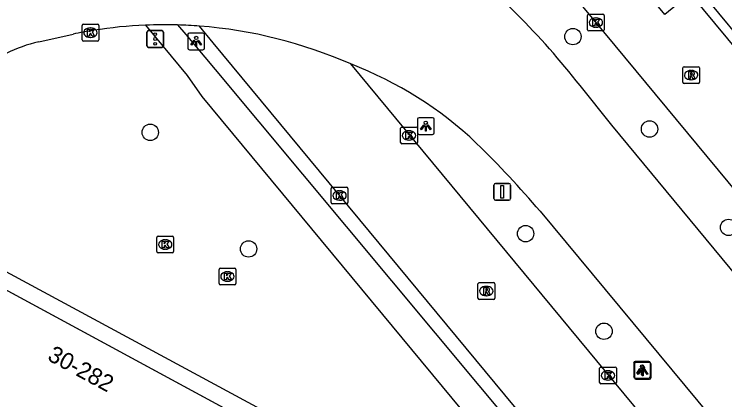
# Model space of a CAD drawing. Extents: x 159489 to 160304, y 383826 to 384530.
# Drawn here: x 159949.7 to 159992.11, y 384232.46 to 384255.48 of the extents above; entities that cross this region are included whole.
import ezdxf

# ---------------------------------------------------------------- set-up
doc = ezdxf.new("R2010")
doc.units = 0
for name, color, linetype in [('IMGEO_Boom', 7, 'Continuous'), ('IMGEO_Fietspad_gesloten', 7, 'Continuous'), ('IMGEO_Kolk', 7, 'Continuous'), ('IMGEO_Lichtpunt', 7, 'Continuous'), ('IMGEO_OVBaan_gesloten', 7, 'Continuous'), ('IMGEO_Pand', 7, 'Continuous'), ('IMGEO_Pand_nummerreeks', 7, 'Continuous'), ('IMGEO_Pand_overbouw', 7, 'Continuous'), ('IMGEO_Rijbaan_lokaal_gesloten', 7, 'Continuous'), ('IMGEO_Rioolput', 7, 'Continuous'), ('IMGEO_Verkeersbordpaal', 7, 'Continuous'), ('IMGEO_Verkeersregelinstallatiepaal', 7, 'Continuous'), ('IMGEO_Voetpad_open', 7, 'Continuous')]:
    doc.layers.add(name, color=color, linetype=linetype)

msp = doc.modelspace()

# ---------------------------------------------------------------- linework, layer by layer
at = {"layer": 'IMGEO_Boom'}
for centre in [(159983.042, 384254.142), (159957.82, 384248.425), (159987.615, 384248.624), (159992.334, 384242.748), (159980.22, 384242.376), (159963.688, 384241.466), (159984.896, 384236.553)]:
    msp.add_circle(centre, 0.489, dxfattribs=at)
at = {"layer": 'IMGEO_Fietspad_gesloten'}
for points in [[(159957.532, 384254.825), (159960.033, 384251.817), (159960.897, 384250.561), (160029.527, 384167.731), (160030.452, 384166.645)], [(159959.452, 384254.838), (159959.937, 384254.261), (159961.686, 384252.179), (160032.453, 384167.34)]]:
    msp.add_lwpolyline(points, dxfattribs=at)
at = {"layer": 'IMGEO_Kolk'}
for p, q in [((159983.91, 384254.552), (159983.91, 384255.404)), ((159983.985, 384255.478), (159984.837, 384255.478)), ((159984.398, 384255.258), (159984.423, 384255.258)), ((159984.911, 384255.404), (159984.911, 384254.552)), ((159953.753, 384253.951), (159953.753, 384254.803)), ((159953.828, 384254.877), (159954.68, 384254.877)), ((159954.754, 384254.803), (159954.754, 384253.951)), ((159954.241, 384254.657), (159954.266, 384254.657)), ((159984.837, 384254.478), (159983.985, 384254.478)), ((159984.421, 384254.698), (159984.396, 384254.698)), ((159954.264, 384254.097), (159954.239, 384254.097)), ((159954.68, 384253.877), (159953.828, 384253.877)), ((159972.761, 384247.814), (159972.761, 384248.666)), ((159972.836, 384248.74), (159973.688, 384248.74)), ((159973.249, 384248.52), (159973.274, 384248.52)), ((159973.762, 384248.666), (159973.762, 384247.814)), ((159973.688, 384247.74), (159972.836, 384247.74)), ((159973.272, 384247.96), (159973.247, 384247.96)), ((159968.614, 384244.23), (159968.614, 384245.082)), ((159968.689, 384245.156), (159969.541, 384245.156)), ((159969.615, 384245.082), (159969.615, 384244.23)), ((159969.102, 384244.936), (159969.127, 384244.936)), ((159969.125, 384244.376), (159969.1, 384244.376)), ((159969.541, 384244.156), (159968.689, 384244.156)), ((159958.212, 384241.304), (159958.212, 384242.156)), ((159958.287, 384242.23), (159959.139, 384242.23)), ((159959.213, 384242.156), (159959.213, 384241.304)), ((159958.7, 384242.01), (159958.725, 384242.01)), ((159959.139, 384241.23), (159958.287, 384241.23)), ((159958.723, 384241.45), (159958.698, 384241.45)), ((159961.929, 384239.393), (159961.929, 384240.245)), ((159962.004, 384240.319), (159962.856, 384240.319)), ((159962.417, 384240.099), (159962.442, 384240.099)), ((159962.93, 384240.245), (159962.93, 384239.393)), ((159962.44, 384239.539), (159962.415, 384239.539)), ((159962.856, 384239.319), (159962.004, 384239.319)), ((159984.638, 384233.485), (159984.638, 384234.337)), ((159984.713, 384234.411), (159985.565, 384234.411)), ((159985.126, 384234.191), (159985.151, 384234.191)), ((159985.639, 384234.337), (159985.639, 384233.485)), ((159985.149, 384233.631), (159985.124, 384233.631)), ((159985.565, 384233.411), (159984.713, 384233.411))]:
    msp.add_line(p, q, dxfattribs=at)
for points in [[(159983.91, 384254.552), (159983.91, 384255.404)], [(159983.985, 384255.478), (159984.837, 384255.478)], [(159984.911, 384255.404), (159984.911, 384254.552)], [(159953.753, 384253.951), (159953.753, 384254.803)], [(159953.828, 384254.877), (159954.68, 384254.877)], [(159954.754, 384254.803), (159954.754, 384253.951)], [(159984.231, 384255.178), (159984.354, 384255.178), (159984.354, 384255.027), (159984.484, 384255.178), (159984.648, 384255.178), (159984.502, 384255.027), (159984.655, 384254.778), (159984.503, 384254.778), (159984.418, 384254.942), (159984.354, 384254.875), (159984.354, 384254.778), (159984.231, 384254.778), (159984.231, 384255.178)], [(159954.074, 384254.577), (159954.197, 384254.577), (159954.197, 384254.426), (159954.327, 384254.577), (159954.491, 384254.577), (159954.345, 384254.426), (159954.498, 384254.177), (159954.346, 384254.177), (159954.261, 384254.341), (159954.197, 384254.274), (159954.197, 384254.177), (159954.074, 384254.177), (159954.074, 384254.577)], [(159984.837, 384254.478), (159983.985, 384254.478)], [(159954.68, 384253.877), (159953.828, 384253.877)], [(159972.761, 384247.814), (159972.761, 384248.666)], [(159972.836, 384248.74), (159973.688, 384248.74)], [(159973.082, 384248.44), (159973.205, 384248.44), (159973.205, 384248.289), (159973.335, 384248.44), (159973.499, 384248.44), (159973.353, 384248.289), (159973.506, 384248.04), (159973.354, 384248.04), (159973.269, 384248.204), (159973.205, 384248.137), (159973.205, 384248.04), (159973.082, 384248.04), (159973.082, 384248.44)], [(159973.762, 384248.666), (159973.762, 384247.814)], [(159973.688, 384247.74), (159972.836, 384247.74)], [(159968.614, 384244.23), (159968.614, 384245.082)], [(159968.689, 384245.156), (159969.541, 384245.156)], [(159969.615, 384245.082), (159969.615, 384244.23)], [(159968.935, 384244.856), (159969.058, 384244.856), (159969.058, 384244.705), (159969.188, 384244.856), (159969.352, 384244.856), (159969.206, 384244.705), (159969.359, 384244.456), (159969.207, 384244.456), (159969.122, 384244.62), (159969.058, 384244.553), (159969.058, 384244.456), (159968.935, 384244.456), (159968.935, 384244.856)], [(159969.541, 384244.156), (159968.689, 384244.156)], [(159958.212, 384241.304), (159958.212, 384242.156)], [(159958.287, 384242.23), (159959.139, 384242.23)], [(159959.213, 384242.156), (159959.213, 384241.304)], [(159958.533, 384241.93), (159958.656, 384241.93), (159958.656, 384241.779), (159958.786, 384241.93), (159958.95, 384241.93), (159958.804, 384241.779), (159958.957, 384241.53), (159958.805, 384241.53), (159958.72, 384241.694), (159958.656, 384241.627), (159958.656, 384241.53), (159958.533, 384241.53), (159958.533, 384241.93)], [(159959.139, 384241.23), (159958.287, 384241.23)], [(159961.929, 384239.393), (159961.929, 384240.245)], [(159962.004, 384240.319), (159962.856, 384240.319)], [(159962.25, 384240.019), (159962.373, 384240.019), (159962.373, 384239.868), (159962.503, 384240.019), (159962.667, 384240.019), (159962.521, 384239.868), (159962.674, 384239.619), (159962.522, 384239.619), (159962.437, 384239.783), (159962.373, 384239.716), (159962.373, 384239.619), (159962.25, 384239.619), (159962.25, 384240.019)], [(159962.93, 384240.245), (159962.93, 384239.393)], [(159962.856, 384239.319), (159962.004, 384239.319)], [(159984.638, 384233.485), (159984.638, 384234.337)], [(159984.713, 384234.411), (159985.565, 384234.411)], [(159984.959, 384234.111), (159985.082, 384234.111), (159985.082, 384233.96), (159985.212, 384234.111), (159985.376, 384234.111), (159985.23, 384233.96), (159985.383, 384233.711), (159985.231, 384233.711), (159985.146, 384233.875), (159985.082, 384233.808), (159985.082, 384233.711), (159984.959, 384233.711), (159984.959, 384234.111)], [(159985.639, 384234.337), (159985.639, 384233.485)], [(159985.565, 384233.411), (159984.713, 384233.411)]]:
    msp.add_lwpolyline(points, dxfattribs=at)
for centre, start, end in [((159983.987, 384255.402), 91.552, 178.448), ((159983.987, 384255.402), 91.552, 178.448), ((159984.835, 384255.402), 1.552, 88.448), ((159984.835, 384255.402), 1.552, 88.448), ((159953.83, 384254.801), 91.552, 178.448), ((159953.83, 384254.801), 91.552, 178.448), ((159954.678, 384254.801), 1.552, 88.448), ((159954.678, 384254.801), 1.552, 88.448), ((159983.987, 384254.554), 181.552, 268.448), ((159983.987, 384254.554), 181.552, 268.448), ((159984.835, 384254.554), 271.552, 358.448), ((159984.835, 384254.554), 271.552, 358.448), ((159953.83, 384253.953), 181.552, 268.448), ((159953.83, 384253.953), 181.552, 268.448), ((159954.678, 384253.953), 271.552, 358.448), ((159954.678, 384253.953), 271.552, 358.448), ((159972.838, 384248.664), 91.552, 178.448), ((159972.838, 384248.664), 91.552, 178.448), ((159973.686, 384248.664), 1.552, 88.448), ((159973.686, 384248.664), 1.552, 88.448), ((159972.838, 384247.816), 181.552, 268.448), ((159972.838, 384247.816), 181.552, 268.448), ((159973.686, 384247.816), 271.552, 358.448), ((159973.686, 384247.816), 271.552, 358.448), ((159968.691, 384245.08), 91.552, 178.448), ((159968.691, 384245.08), 91.552, 178.448), ((159969.539, 384245.08), 1.552, 88.448), ((159969.539, 384245.08), 1.552, 88.448), ((159968.691, 384244.232), 181.552, 268.448), ((159968.691, 384244.232), 181.552, 268.448), ((159969.539, 384244.232), 271.552, 358.448), ((159969.539, 384244.232), 271.552, 358.448), ((159958.289, 384242.154), 91.552, 178.448), ((159958.289, 384242.154), 91.552, 178.448), ((159959.137, 384242.154), 1.552, 88.448), ((159959.137, 384242.154), 1.552, 88.448), ((159958.289, 384241.306), 181.552, 268.448), ((159958.289, 384241.306), 181.552, 268.448), ((159959.137, 384241.306), 271.552, 358.448), ((159959.137, 384241.306), 271.552, 358.448), ((159962.006, 384240.243), 91.552, 178.448), ((159962.006, 384240.243), 91.552, 178.448), ((159962.854, 384240.243), 1.552, 88.448), ((159962.854, 384240.243), 1.552, 88.448), ((159962.006, 384239.395), 181.552, 268.448), ((159962.006, 384239.395), 181.552, 268.448), ((159962.854, 384239.395), 271.552, 358.448), ((159962.854, 384239.395), 271.552, 358.448), ((159984.715, 384234.335), 91.552, 178.448), ((159984.715, 384234.335), 91.552, 178.448), ((159985.563, 384234.335), 1.552, 88.448), ((159985.563, 384234.335), 1.552, 88.448), ((159984.715, 384233.487), 181.552, 268.448), ((159984.715, 384233.487), 181.552, 268.448), ((159985.563, 384233.487), 271.552, 358.448), ((159985.563, 384233.487), 271.552, 358.448)]:
    msp.add_arc(centre, 0.0765, start, end, dxfattribs=at)
for centre, major_axis, ratio, start_param, end_param in [((159984.397, 384254.978), (-0.387, 0.002), 0.722429, 4.712389, 7.853982), ((159984.422, 384254.978), (-0.39, 0.002), 0.717154, 1.570796, 4.712389), ((159954.24, 384254.377), (-0.387, 0.002), 0.722429, 4.712389, 7.853982), ((159954.265, 384254.377), (-0.39, 0.002), 0.717154, 1.570796, 4.712389), ((159973.248, 384248.24), (-0.387, 0.002), 0.722429, 4.712389, 7.853982), ((159973.273, 384248.24), (-0.39, 0.002), 0.717154, 1.570796, 4.712389), ((159969.101, 384244.656), (-0.387, 0.002), 0.722429, 4.712389, 7.853982), ((159969.126, 384244.656), (-0.39, 0.002), 0.717154, 1.570796, 4.712389), ((159958.699, 384241.73), (-0.387, 0.002), 0.722429, 4.712389, 7.853982), ((159958.724, 384241.73), (-0.39, 0.002), 0.717154, 1.570796, 4.712389), ((159962.416, 384239.819), (-0.387, 0.002), 0.722429, 4.712389, 7.853982), ((159962.441, 384239.819), (-0.39, 0.002), 0.717154, 1.570796, 4.712389), ((159985.125, 384233.911), (-0.387, 0.002), 0.722429, 4.712389, 7.853982), ((159985.15, 384233.911), (-0.39, 0.002), 0.717154, 1.570796, 4.712389)]:
    msp.add_ellipse(centre, major_axis=major_axis, ratio=ratio, start_param=start_param, end_param=end_param, dxfattribs=at)
at = {"layer": 'IMGEO_Lichtpunt'}
for p, q in [((159960.967, 384254.356), (159960.159, 384254.356)), ((159960.967, 384254.356), (159960.159, 384254.356)), ((159960.065, 384254.261), (159960.065, 384253.454)), ((159960.065, 384254.261), (159960.065, 384253.454)), ((159961.061, 384253.454), (159961.061, 384254.261)), ((159961.061, 384253.454), (159961.061, 384254.261)), ((159960.159, 384253.36), (159960.967, 384253.36)), ((159960.159, 384253.36), (159960.967, 384253.36)), ((159974.667, 384249.3), (159973.859, 384249.3)), ((159974.667, 384249.3), (159973.859, 384249.3)), ((159973.765, 384249.205), (159973.765, 384248.398)), ((159973.765, 384249.205), (159973.765, 384248.398)), ((159974.761, 384248.398), (159974.761, 384249.205)), ((159974.761, 384248.398), (159974.761, 384249.205)), ((159973.859, 384248.304), (159974.667, 384248.304)), ((159973.859, 384248.304), (159974.667, 384248.304)), ((159986.668, 384234.654), (159986.668, 384233.847)), ((159986.668, 384234.654), (159986.668, 384233.847)), ((159986.709, 384234.59), (159986.709, 384233.783)), ((159986.709, 384234.59), (159986.709, 384233.783)), ((159987.57, 384234.749), (159986.762, 384234.749)), ((159987.57, 384234.749), (159986.762, 384234.749)), ((159987.611, 384234.685), (159986.803, 384234.685)), ((159987.611, 384234.685), (159986.803, 384234.685)), ((159987.664, 384233.847), (159987.664, 384234.654)), ((159987.664, 384233.847), (159987.664, 384234.654)), ((159987.705, 384233.783), (159987.705, 384234.59)), ((159987.705, 384233.783), (159987.705, 384234.59)), ((159986.762, 384233.753), (159987.57, 384233.753)), ((159986.762, 384233.753), (159987.57, 384233.753)), ((159986.803, 384233.689), (159987.611, 384233.689)), ((159986.803, 384233.689), (159987.611, 384233.689))]:
    msp.add_line(p, q, dxfattribs=at)
for points in [[(159960.439, 384253.925), (159960.478, 384253.897), (159960.29, 384253.635), (159960.252, 384253.662), (159960.439, 384253.925)], [(159960.651, 384253.897), (159960.689, 384253.924), (159960.876, 384253.662), (159960.837, 384253.634), (159960.651, 384253.897)], [(159960.541, 384253.877), (159960.588, 384253.877), (159960.588, 384253.555), (159960.541, 384253.555), (159960.541, 384253.877)], [(159974.139, 384248.869), (159974.178, 384248.841), (159973.99, 384248.579), (159973.952, 384248.606), (159974.139, 384248.869)], [(159974.351, 384248.841), (159974.389, 384248.868), (159974.576, 384248.606), (159974.537, 384248.578), (159974.351, 384248.841)], [(159974.241, 384248.821), (159974.288, 384248.821), (159974.288, 384248.499), (159974.241, 384248.499), (159974.241, 384248.821)], [(159987.042, 384234.318), (159987.081, 384234.29), (159986.893, 384234.028), (159986.855, 384234.055), (159987.042, 384234.318)], [(159987.083, 384234.254), (159987.122, 384234.226), (159986.934, 384233.964), (159986.896, 384233.991), (159987.083, 384234.254)], [(159987.144, 384234.27), (159987.191, 384234.27), (159987.191, 384233.948), (159987.144, 384233.948), (159987.144, 384234.27)], [(159987.185, 384234.206), (159987.232, 384234.206), (159987.232, 384233.884), (159987.185, 384233.884), (159987.185, 384234.206)], [(159987.254, 384234.29), (159987.292, 384234.317), (159987.479, 384234.055), (159987.44, 384234.027), (159987.254, 384234.29)], [(159987.295, 384234.226), (159987.333, 384234.253), (159987.52, 384233.991), (159987.481, 384233.963), (159987.295, 384234.226)]]:
    msp.add_lwpolyline(points, dxfattribs=at)
for centre in [(159960.564, 384254.059), (159974.264, 384249.003), (159987.167, 384234.452), (159987.208, 384234.388)]:
    msp.add_circle(centre, 0.0994, dxfattribs=at)
for centre, start, end in [((159960.159, 384254.261), 90, 180), ((159960.159, 384254.261), 90, 180), ((159960.967, 384254.261), 0, 90), ((159960.967, 384254.261), 0, 90), ((159960.159, 384253.454), 180, 270), ((159960.159, 384253.454), 180, 270), ((159960.967, 384253.454), 270, 0), ((159960.967, 384253.454), 270, 360), ((159973.859, 384249.205), 90, 180), ((159973.859, 384249.205), 90, 180), ((159974.667, 384249.205), 0, 90), ((159974.667, 384249.205), 0, 90), ((159973.859, 384248.398), 180, 270), ((159973.859, 384248.398), 180, 270), ((159974.667, 384248.398), 270, 0), ((159974.667, 384248.398), 270, 360), ((159986.762, 384234.654), 90, 180), ((159986.762, 384234.654), 90, 180), ((159986.803, 384234.59), 90, 180), ((159986.803, 384234.59), 90, 180), ((159987.57, 384234.654), 0, 90), ((159987.57, 384234.654), 0, 90), ((159987.611, 384234.59), 0, 90), ((159987.611, 384234.59), 0, 90), ((159986.762, 384233.847), 180, 270), ((159986.762, 384233.847), 180, 270), ((159986.803, 384233.783), 180, 270), ((159986.803, 384233.783), 180, 270), ((159987.57, 384233.847), 270, 0), ((159987.57, 384233.847), 270, 360), ((159987.611, 384233.783), 270, 0), ((159987.611, 384233.783), 270, 360)]:
    msp.add_arc(centre, 0.0946, start, end, dxfattribs=at)
at = {"layer": 'IMGEO_OVBaan_gesloten'}
for points in [[(159951.164, 384253.832), (159953.211, 384254.289)], [(160035.565, 384188.31), (160015.314, 384212.637), (159985.373, 384248.854), (159983.467, 384251.216)], [(159981.084, 384243.71), (160030.552, 384184.07)]]:
    msp.add_lwpolyline(points, dxfattribs=at)
for centre, radius, start, end in [((159946.501, 384222.347), 46.903, 37.9888, 51.9544), ((159958.697, 384227.713), 27.137, 92.4615, 98.9856), ((159958.681, 384226.911), 27.937, 88.4187, 92.3572), ((159958.68, 384228.095), 26.754, 85.5364, 88.3462), ((159958.952, 384226.397), 28.477, 99.0769, 101.6297), ((159958.606, 384227.036), 27.816, 66.3012, 85.5546), ((159953.25, 384245.014), 9.062, 103.3066, 116.3894), ((159961.544, 384231.122), 22.918, 46.5819, 68.9231), ((159935.476, 384204.934), 59.864, 40.37157, 45.68661)]:
    msp.add_arc(centre, radius, start, end, dxfattribs=at)
at = {"layer": 'IMGEO_Pand'}
msp.add_lwpolyline([(159928.39, 384211.596), (159944.524, 384241.543), (159967.686, 384229.02)], dxfattribs=at)
at = {"layer": 'IMGEO_Pand_overbouw'}
msp.add_lwpolyline([(159953.299, 384198.181), (159969.896, 384228.943), (159943.238, 384243.325), (159926.605, 384212.558), (159928.39, 384211.596), (159944.07, 384240.7), (159944.524, 384241.543), (159945.039, 384241.265), (159967.686, 384229.02), (159951.577, 384199.109)], close=True, dxfattribs=at)
at = {"layer": 'IMGEO_Rijbaan_lokaal_gesloten'}
for points in [[(159964.53, 384278.991), (160037.958, 384190.34)], [(159990.035, 384256.71), (159988.52, 384255.456), (159973.268, 384273.877), (159974.782, 384275.132)], [(159990.035, 384256.71), (159994.505, 384251.312)], [(160030.037, 384171.103), (159961.57, 384253.773), (159960.762, 384254.768)], [(160028.141, 384182.05), (159969.786, 384252.506)]]:
    msp.add_lwpolyline(points, dxfattribs=at)
at = {"layer": 'IMGEO_Rioolput'}
for p, q in [((159989.598, 384251.418), (159989.598, 384252.27)), ((159989.673, 384252.344), (159990.525, 384252.344)), ((159990.599, 384252.27), (159990.599, 384251.418)), ((159990.086, 384252.124), (159990.111, 384252.124)), ((159990.109, 384251.564), (159990.084, 384251.564)), ((159990.525, 384251.344), (159989.673, 384251.344)), ((159977.377, 384238.526), (159977.377, 384239.378)), ((159977.452, 384239.452), (159978.304, 384239.452)), ((159977.865, 384239.232), (159977.89, 384239.232)), ((159978.378, 384239.378), (159978.378, 384238.526)), ((159977.888, 384238.672), (159977.863, 384238.672)), ((159978.304, 384238.452), (159977.452, 384238.452))]:
    msp.add_line(p, q, dxfattribs=at)
for points in [[(159989.598, 384251.418), (159989.598, 384252.27)], [(159989.673, 384252.344), (159990.525, 384252.344)], [(159990.599, 384252.27), (159990.599, 384251.418)], [(159990.187, 384252.042), (159989.935, 384252.044), (159989.935, 384251.644)], [(159989.935, 384251.644), (159990.059, 384251.644), (159990.059, 384251.806), (159990.07, 384251.806)], [(159990.113, 384251.963), (159990.059, 384251.963), (159990.059, 384251.882)], [(159990.059, 384251.882), (159990.111, 384251.882)], [(159990.117, 384251.777), (159990.188, 384251.644), (159990.328, 384251.644), (159990.263, 384251.77)], [(159990.525, 384251.344), (159989.673, 384251.344)], [(159977.377, 384238.526), (159977.377, 384239.378)], [(159977.452, 384239.452), (159978.304, 384239.452)], [(159977.966, 384239.15), (159977.714, 384239.152), (159977.714, 384238.752)], [(159978.378, 384239.378), (159978.378, 384238.526)], [(159977.714, 384238.752), (159977.838, 384238.752), (159977.838, 384238.914), (159977.849, 384238.914)], [(159977.892, 384239.071), (159977.838, 384239.071), (159977.838, 384238.99)], [(159977.838, 384238.99), (159977.89, 384238.99)], [(159977.896, 384238.885), (159977.967, 384238.752), (159978.107, 384238.752), (159978.042, 384238.878)], [(159978.304, 384238.452), (159977.452, 384238.452)]]:
    msp.add_lwpolyline(points, dxfattribs=at)
for centre, radius, start, end in [((159989.675, 384252.268), 0.0765, 91.552, 178.448), ((159989.675, 384252.268), 0.0765, 91.552, 178.448), ((159990.523, 384252.268), 0.0765, 1.552, 88.448), ((159990.523, 384252.268), 0.0765, 1.552, 88.448), ((159990.069, 384251.753), 0.0533, 26.0293, 88.6989), ((159990.095, 384252.071), 0.19, 274.7715, 282.9687), ((159990.119, 384251.867), 0.0964, 77.0061, 93.1865), ((159990.133, 384251.924), 0.0378, 276.6634, 79.6772), ((159990.186, 384251.932), 0.109, 350.3612, 89.416), ((159990.184, 384251.932), 0.112, 277.5842, 350.9817), ((159990.168, 384251.717), 0.108, 29.5134, 73.7905), ((159989.675, 384251.42), 0.0765, 181.552, 268.448), ((159989.675, 384251.42), 0.0765, 181.552, 268.448), ((159990.523, 384251.42), 0.0765, 271.552, 358.448), ((159990.523, 384251.42), 0.0765, 271.552, 358.448), ((159977.454, 384239.376), 0.0765, 91.552, 178.448), ((159977.454, 384239.376), 0.0765, 91.552, 178.448), ((159977.965, 384239.04), 0.109, 350.3612, 89.416), ((159978.302, 384239.376), 0.0765, 1.552, 88.448), ((159978.302, 384239.376), 0.0765, 1.552, 88.448), ((159977.848, 384238.861), 0.0533, 26.0293, 88.6989), ((159977.874, 384239.179), 0.19, 274.7715, 282.9687), ((159977.898, 384238.975), 0.0964, 77.0061, 93.1865), ((159977.912, 384239.032), 0.0378, 276.6634, 79.6772), ((159977.963, 384239.04), 0.112, 277.5842, 350.9817), ((159977.947, 384238.825), 0.108, 29.5134, 73.7905), ((159977.454, 384238.528), 0.0765, 181.552, 268.448), ((159977.454, 384238.528), 0.0765, 181.552, 268.448), ((159978.302, 384238.528), 0.0765, 271.552, 358.448), ((159978.302, 384238.528), 0.0765, 271.552, 358.448)]:
    msp.add_arc(centre, radius, start, end, dxfattribs=at)
for centre, major_axis, ratio, start_param, end_param in [((159990.085, 384251.844), (-0.387, 0.002), 0.722429, 4.712389, 7.853982), ((159990.11, 384251.844), (-0.39, 0.002), 0.717154, 1.570796, 4.712389), ((159977.864, 384238.952), (-0.387, 0.002), 0.722429, 4.712389, 7.853982), ((159977.889, 384238.952), (-0.39, 0.002), 0.717154, 1.570796, 4.712389)]:
    msp.add_ellipse(centre, major_axis=major_axis, ratio=ratio, start_param=start_param, end_param=end_param, dxfattribs=at)
at = {"layer": 'IMGEO_Verkeersbordpaal'}
for p, q in [((159978.331, 384244.472), (159978.331, 384245.272)), ((159978.331, 384245.272), (159978.331, 384244.472)), ((159978.431, 384245.372), (159979.221, 384245.372)), ((159979.221, 384245.372), (159978.431, 384245.372)), ((159979.321, 384245.272), (159979.321, 384244.472)), ((159979.321, 384244.472), (159979.321, 384245.272)), ((159979.221, 384244.372), (159978.431, 384244.372)), ((159978.431, 384244.372), (159979.221, 384244.372))]:
    msp.add_line(p, q, dxfattribs=at)
msp.add_lwpolyline([(159978.751, 384245.247), (159978.901, 384245.247), (159978.901, 384244.497), (159978.751, 384244.497), (159978.751, 384245.247)], dxfattribs=at)
for centre, start, end in [((159978.431, 384245.272), 90, 180), ((159978.431, 384245.272), 90, 180), ((159979.221, 384245.272), 0, 90), ((159979.221, 384245.272), 360, 90), ((159978.431, 384244.472), 180, 270), ((159978.431, 384244.472), 180, 270), ((159979.221, 384244.472), 270, 0), ((159979.221, 384244.472), 270, 0)]:
    msp.add_arc(centre, 0.1, start, end, dxfattribs=at)
at = {"layer": 'IMGEO_Verkeersregelinstallatiepaal'}
for p, q in [((159957.62, 384253.598), (159957.62, 384254.398)), ((159957.62, 384254.398), (159957.62, 384253.598)), ((159957.72, 384254.498), (159958.51, 384254.498)), ((159958.51, 384254.498), (159957.72, 384254.498)), ((159958.61, 384254.398), (159958.61, 384253.598)), ((159958.61, 384253.598), (159958.61, 384254.398)), ((159958.51, 384253.498), (159957.72, 384253.498)), ((159957.72, 384253.498), (159958.51, 384253.498))]:
    msp.add_line(p, q, dxfattribs=at)
for centre in [(159958.115, 384254.288), (159958.115, 384253.998), (159958.115, 384253.708)]:
    msp.add_circle(centre, 0.085, dxfattribs=at)
for centre, start, end in [((159957.72, 384254.398), 90, 180), ((159957.72, 384254.398), 90, 180), ((159958.51, 384254.398), 0, 90), ((159958.51, 384254.398), 360, 90), ((159957.72, 384253.598), 180, 270), ((159957.72, 384253.598), 180, 270), ((159958.51, 384253.598), 270, 0), ((159958.51, 384253.598), 270, 0)]:
    msp.add_arc(centre, 0.1, start, end, dxfattribs=at)
at = {"layer": 'IMGEO_Voetpad_open'}
msp.add_lwpolyline([(159937.427, 384324.203), (159935.905, 384322.929), (160048.804, 384186.671)], dxfattribs=at)

# ---------------------------------------------------------------- texts
at = {"layer": 'IMGEO_Pand_nummerreeks'}
msp.add_text('30-282', height=1, rotation=331.5985, dxfattribs=at).set_placement((159951.624, 384234.863))

doc.saveas('drawing.dxf')
